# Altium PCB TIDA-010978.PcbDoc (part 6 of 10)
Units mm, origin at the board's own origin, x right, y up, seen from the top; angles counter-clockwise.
Board outline 243.95 x 94.85 mm, 4 copper layers (Top Layer, Mid Layer 1, Mid Layer 2, Bottom Layer), stack 1.623 mm thick; 865 components, 374 nets, 2308 pads, 2132 vias.
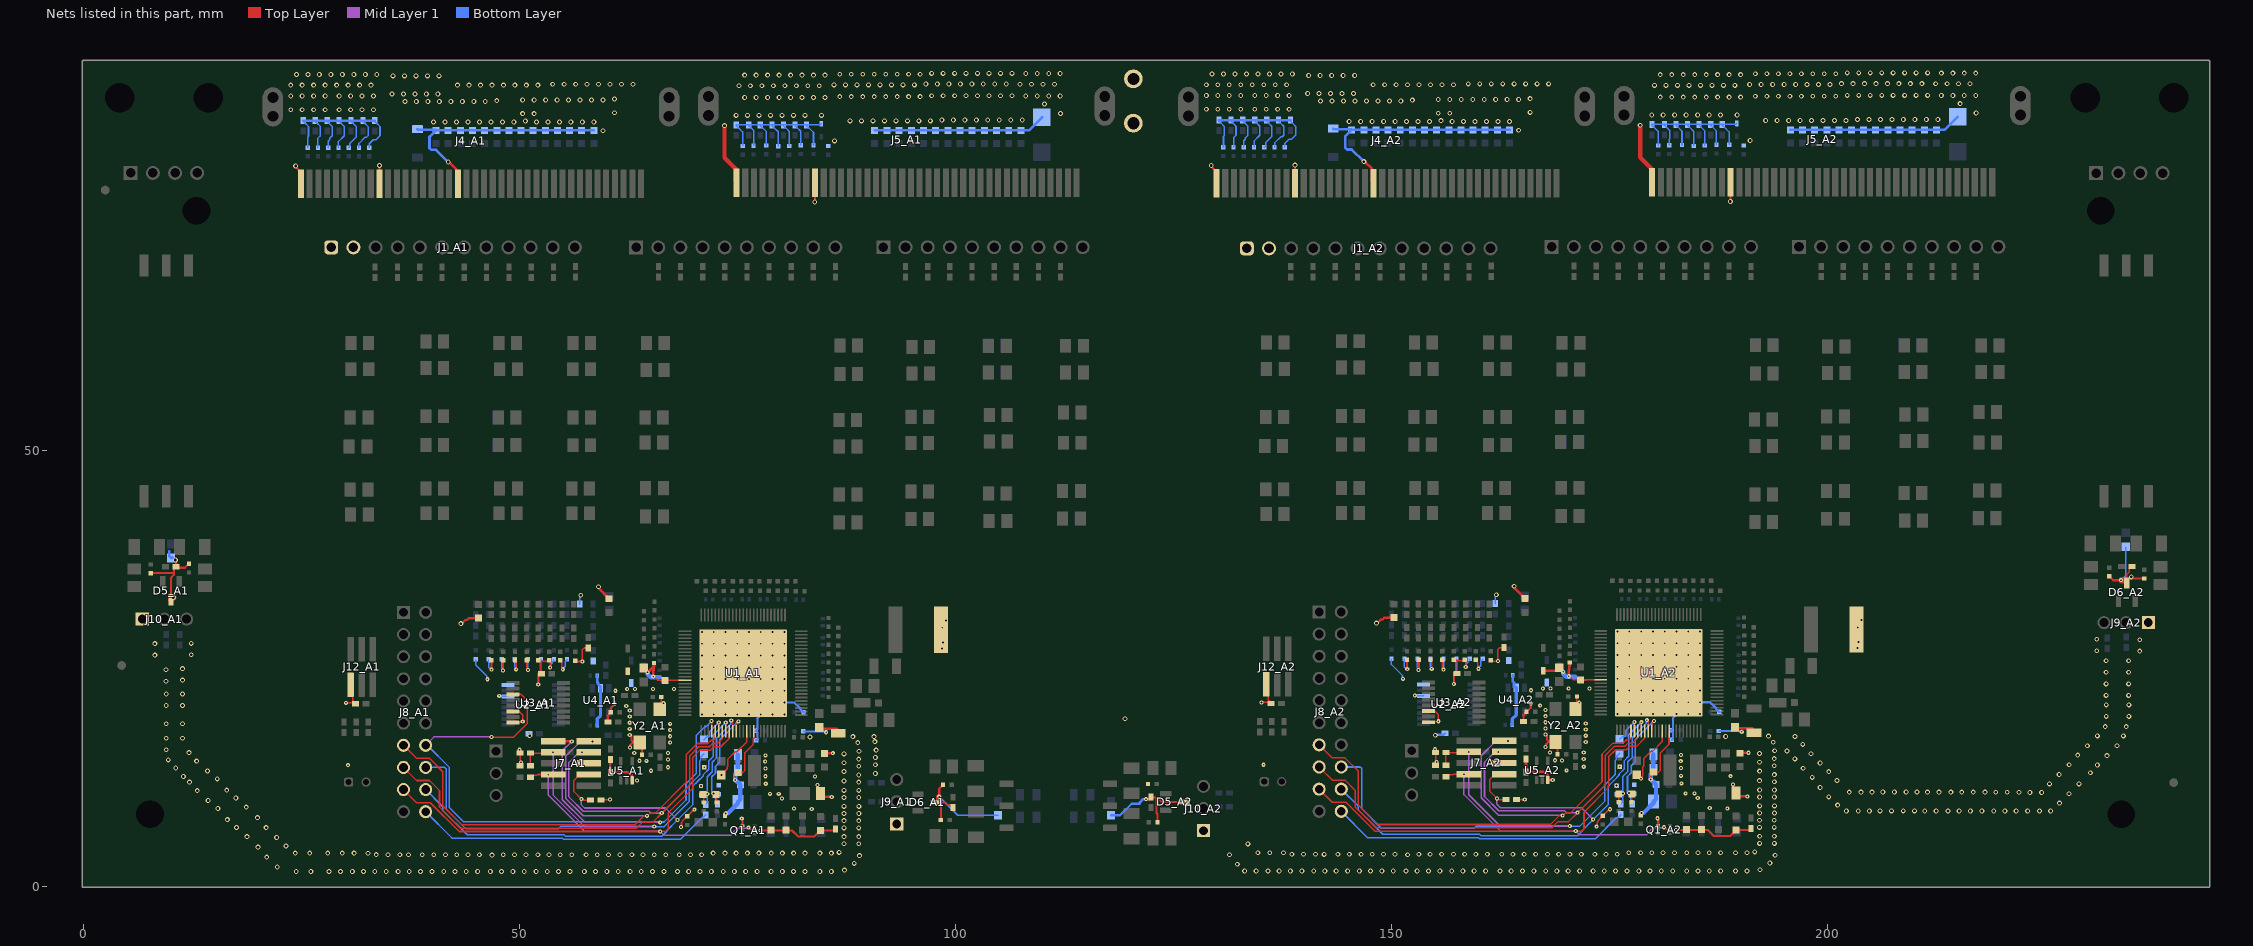
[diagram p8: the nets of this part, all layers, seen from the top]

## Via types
v1: diameter 0.559, hole 0.305, Top Layer to Bottom Layer, tented both sides, 1735 vias
v2: diameter 0.47, hole 0.2, Top Layer to Bottom Layer, tented both sides, 269 vias
v3: diameter 0.5, hole 0.2, Top Layer to Bottom Layer, tented both sides, 128 vias

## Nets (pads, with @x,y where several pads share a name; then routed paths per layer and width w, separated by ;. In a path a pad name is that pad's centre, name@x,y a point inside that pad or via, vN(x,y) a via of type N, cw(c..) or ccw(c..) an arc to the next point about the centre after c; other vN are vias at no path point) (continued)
GND_A1: AVDD_LED1_A1.1 C3.1 C4.1 C9_A1.1 C10_A1.2 C11_A1.1 C16_A1.1 C17_A1.1 C18_A1.2 C19_A1.1 C20_A1.1 C21_A1.1 C22_A1.1 C23_A1.1 C24_A1.1 C29_A1.1 C30_A1.1 C32_A1.2 C33_A1.2 C40_A1.1 C51_A1.2 C52_A1.1 C58_A1.1 C59_A1.2 C60_A1.2 C61_A1.2 C62_A1.2 C63_A1.2 C64_A1.2 C65_A1.2 C66_A1.2 C67_A1.2 C68_A1.2 C69_A1.2 C70_A1.1 C71_A1.1 C72_A1.2 C73_A1.2 C74_A1.1 C75_A1.1 C76_A1.2 C77_A1.2 C78_A1.1 C79_A1.1 C80_A1.2 C81_A1.2 C82_A1.1 C83_A1.1 C84_A1.1 C85_A1.1 C86_A1.1 C87_A1.1 C88_A1.2 C89_A1.1 C90_A1.1 C92_A1.1 C93_A1.1 C94_A1.2 C95_A1.1 C96_A1.1 C98_A1.1 C99_A1.1 C102_A1.1 C103_A1.1 C104_A1.1 C105_A1.1 C108_A1.1 C109_A1.1 C112_A1.1 C113_A1.1 C114_A1.1 C115_A1.1 C118_A1.1 C119_A1.1 C123_A1.1 C124_A1.2 C125_A1.1 C128_A1.2 C129_A1.1 C132_A1.1 C133_A1.1 C134_A1.1 C135_A1.1 C138_A1.2 C139_A1.2 C140_A1.1 C141_A1.1 C142_A1.2 C143_A1.1 C146_A1.1 C147_A1.2 C148_A1.2 C149_A1.1 C150_A1.1 C151_A1.1 C154_A1.1 C155_A1.1 C158_A1.1 C159_A1.2 C160_A1.2 C161_A1.1 C164_A1.1 D1_A1.2 D3_A1.2 D4_A1.2 D5_A1.3 D6_A1.3 D7_A1.2 D8_A1.2 J1_A1.1 J1_A1.2 J4_A1.5 J4_A1.21 J4_A1.30 J5_A1.5 J5_A1.21 J7_A1.5 J9_A1.1 J10_A1.1 J12_A1.6 j13.1 LDOIN_LED1_A1.1 NFAULT_LED1_A1.1 Q1_A1.1 R76_A1.1 R79_A1.1 R141_A1.2 R144_A1.2 R147_A1.2 R150_A1.2 R153_A1.1 R157_A1.2 R160_A1.2 R162_A1.2 R164_A1.2 R165_A1.1 R177_A1.2 R179_A1.2 R181_A1.2 R183_A1.2 R185_A1.1 R187_A1.2 R189_A1.2 R191_A1.2 R236_A1.1 RT1_A1.2 TSREF_LED1_A1.1 U1_A1.65 U1_A1.89 U1_A1.91 U1_A1.101 U2_A1.6 U2_A1.8 U3_A1.6 U3_A1.8 U4_A1.2 U5_A1.3 Y2_A1.2 Y2_A1.4 | length 266.7
  Top Layer w0.178: v2(30.107,21.044) 31.072,21.044 R236_A1.1@31.136,20.98 ; J12_A1.6@30.631,23.126 30.875,22.882 R236_A1.1@30.875,21.141 ; 30.87,21.255 30.97,21.255 R236_A1.1@31.181,21.044 ; U3_A1.8@49.243,18.774 49.299,18.829 50.316,18.829 v2(50.372,18.885) 50.372,19.668 50.088,19.952 49.365,19.952 U3_A1.6@49.243,20.074 ; C80_A1.2@49.482,25.822 49.624,25.681 v2(49.624,24.893) ; R162_A1.2@50.05,13.845 50.071,13.866 C32_A1.2@50.071,15.296 ; C76_A1.2@50.832,25.822 50.832,25.017 50.967,24.882 v2(50.967,24.803) ; v2(52.153,23.151) 52.191,23.19 52.191,24.162 52.394,24.365 C88_A1.2@52.435,24.365 ; C88_A1.2@52.503,24.373 52.444,24.373 C88_A1.2@52.435,24.365 ; v2(53.52,25.113) 53.52,25.705 53.403,25.822 52.162,25.822 52.373,25.611 52.373,24.428 C88_A1.2@52.435,24.365 ; C68_A1.2@54.664,25.822 54.875,25.611 54.875,25.077 54.971,24.982 v2(54.971,24.903) ; C73_A1.2@56.387,25.793 56.387,25.787 v2(57.207,25.787) 57.207,27.132 57.409,27.334 R185_A1.1@57.902,27.334 ; R165_A1.1@59.346,9.902 59.4,9.956 v2(60.397,9.956) ; TSREF_LED1_A1.1@60.292,32.984 TSREF_LED1_A1.1@60.604,32.673 ; v2@65.416,24.049 65.816,23.648 66.685,23.648 C30_A1.1@66.704,23.629 ; Y2_A1.2@66.094,20.313 66.272,20.491 C128_A1.2@66.272,21.722 ; C30_A1.1@66.704,23.615 67.334,23.615 67.367,23.649 U1_A1.65@68.982,23.649 ; v2(68.528,6.8) 68.584,6.856 68.584,7.291 68.651,7.358 68.651,7.462 69.988,8.799 v2(70.055,8.799) ; C21_A1.1@73.142,12.79 73.835,13.483 73.835,13.675 73.906,13.745 73.906,14.597 74.737,15.428 74.924,15.428 76.057,16.561 U1_A1.89@76.057,17.774 ; C40_A1.1@73.615,8.307 v2(73.671,8.363) ; v2(74.737,12.212) 74.761,12.236 74.761,12.774 C22_A1.1@75.044,13.057 75.628,13.057 75.819,13.247 75.819,15.254 76.824,16.259 76.824,16.925 76.856,16.957 76.856,17.772 U1_A1.91@76.857,17.774 ; D6_A1.3@98.325,9.621 98.786,9.621 99.075,9.333 99.497,9.333 99.708,9.121 C143_A1.1@99.708,9.021
  Top Layer w0.254: C149_A1.1@7.717,35.916 7.745,35.944 10.371,35.944 ; D5_A1.3@10.044,33.134 10.044,35.399 10.371,35.726 10.371,35.944 ; 10.371,36.172 10.371,35.944 ; 10.372,36.172 10.372,36.493 10.545,36.666 C142_A1.2@10.633,36.666 ; v1(10.541,37.436) 10.541,37.353 10.645,37.25 10.645,36.666 10.779,36.531 11.628,36.531 C148_A1.2@12.096,37 ; v1(24.331,82.609) 24.39,82.551 24.39,82.44 24.942,81.887 J4_A1.21@24.942,80.587 ; J4_A1.5@33.942,80.587 v1(33.942,82.659) ; v1(43.284,30.133) 43.366,30.133 43.789,30.556 43.974,30.556 44.171,30.753 C24_A1.1@45.296,30.753 ; C77_A1.2@46.781,25.822 46.794,25.809 46.794,24.869 v2(46.807,24.856) ; v2(48.11,24.756) 48.119,24.764 48.119,25.814 C81_A1.2@48.127,25.822 ; R76_A1.1@60.128,18.845 60.128,19.604 C155_A1.1@60.483,19.959 60.483,20.456 v2@60.966,20.939 ; v2(62.672,15.937) 62.713,15.979 62.713,16.216 63.041,16.545 ; v2@62.814,17.364 62.837,17.341 62.837,16.748 63.041,16.545 ; C124_A1.2@64.047,15.088 64.047,16.261 Y2_A1.4@63.794,16.513 63.763,16.545 63.041,16.545 ; C21_A1.1@73.142,12.79 C21_A1.1@73.142,12.765 73.154,12.765 v2(73.156,12.763) ; v2(75.494,7.764) 75.494,7.705 75.587,7.612 Q1_A1.1@75.587,6.965 ; v2(77.639,6.415) 80.524,6.415 LDOIN_LED1_A1.1@80.571,6.462 80.621,6.412 81.267,6.412 81.944,5.735 83.84,5.735 NFAULT_LED1_A1.1@84.517,6.412 86.078,6.412 R79_A1.1@86.233,6.567 ; v1(83.863,78.487) 83.878,78.501 83.878,80.673 J5_A1.5@83.892,80.687 ; C9_A1.1@84.393,18.214 84.521,18.086 85.193,18.086 ; D3_A1.2@84.519,10.671 84.903,10.287 85.768,10.287 v2(85.81,10.246) ; C20_A1.1@84.958,15.215 85.021,15.277 v2(85.933,15.277) ; v2(85.171,17.674) 85.193,17.697 85.193,18.086 ; C19_A1.1@86.559,17.937 86.411,18.086 85.193,18.086 ; D6_A1.3@97.804,9.621 97.956,9.621 D6_A1.3@98.129,9.794 ; C154_A1.1@98.325,7.612 98.325,9.621 98.325,10.029 98.129,10.226 v2(98.129,10.284) 98.129,11.19 C147_A1.2@98.575,11.636
  Top Layer w0.305: v1(41.831,83.062) 41.88,83.013 41.986,83.013 42.745,82.254 42.745,80.785 J4_A1.30@42.942,80.587 ; v1(59.069,34.361) 59.118,34.313 59.118,34.159 TSREF_LED1_A1.1@60.292,32.984 ; C161_A1.1@60.428,14.557 C160_A1.2@60.428,13.078 62.51,13.078 62.889,12.699 62.889,12.205 U5_A1.3@62.937,12.157 ; v2(64.689,24.548) 64.711,24.548 65.339,25.177 ; v2(65.344,24.049) 65.344,24.741 65.38,24.777 65.38,25.191 65.435,25.246 65.435,25.62 C164_A1.1@65.437,25.623
  Top Layer w0.508: v1(73.517,87.237) 73.517,83.547 74.796,82.267 74.796,80.783 J5_A1.21@74.892,80.687
  Top Layer w0.711: D5_A1.3@10.044,32.867 v1(10.311,33.134) ; D6_A1.3@98.129,9.794 v2@98.129,10.226
  Bottom Layer w0.178: R181_A1.2@25.217,87.812 25.217,87.712 25.428,87.501 25.437,87.501 25.806,87.132 25.806,86.036 25.738,85.968 25.738,84.735 C102_A1.1@25.715,84.712 ; R177_A1.2@26.584,87.812 26.584,87.712 26.795,87.501 26.804,87.501 27.173,87.132 27.173,86.092 26.89,85.81 C95_A1.1@26.89,84.712 ; R179_A1.2@27.951,87.812 27.951,87.712 28.162,87.501 28.17,87.501 28.54,87.132 28.54,86.092 28.227,85.78 28.227,85.615 28.066,85.453 C98_A1.1@28.066,84.712 ; C104_A1.1@29.241,84.712 29.241,85.427 29.906,86.092 29.906,87.132 29.537,87.501 29.528,87.501 29.317,87.712 R183_A1.2@29.317,87.812 ; C108_A1.1@30.416,84.712 30.559,84.854 30.559,85.229 31.273,85.943 31.273,87.132 30.904,87.501 30.895,87.501 30.684,87.712 R187_A1.2@30.684,87.812 ; C112_A1.1@31.592,84.712 31.592,85.193 32.322,85.923 32.47,85.923 32.64,86.092 32.64,87.132 32.27,87.501 32.262,87.501 32.051,87.712 R189_A1.2@32.051,87.812 ; C114_A1.1@32.767,84.712 32.767,85.151 33.238,85.622 33.536,85.622 34.006,86.092 34.006,87.132 33.637,87.501 33.628,87.501 33.417,87.712 R191_A1.2@33.417,87.812 ; C64_A1.2@44.997,25.965 44.997,25.391 46.263,24.125 46.263,23.808 v2(46.319,23.753) ; C66_A1.2@46.491,25.965 46.491,25.054 46.53,25.054 46.728,24.856 v2(46.807,24.856) ; v2@47.728,21.904 47.812,21.82 48.642,21.82 U2_A1.6@48.673,21.789 ; C65_A1.2@47.984,25.965 47.984,24.961 48.11,24.835 v2(48.11,24.756) ; C63_A1.2@49.477,25.965 49.477,25.118 49.624,24.972 v2(49.624,24.893) ; v2(50.967,24.803) 50.967,25.961 C61_A1.2@50.971,25.965 ; v2(52.153,23.151) 52.153,24.411 52.464,24.723 52.464,25.904 C60_A1.2@52.464,25.965 ; v2(53.52,25.113) 53.576,25.169 53.576,25.483 53.958,25.865 C59_A1.2@53.958,25.965 ; v2(54.971,24.903) 54.971,24.982 55.24,25.251 55.24,25.754 C62_A1.2@55.451,25.965 ; R153_A1.1@56.902,32.371 56.902,33.157 57.03,33.285 v1(57.03,33.388) ; C158_A1.1@58.902,24.162 C158_A1.1@58.969,24.229 ; v2(65.344,24.049) v2@65.395,24.1 ; C82_A1.1@75.592,84.912 75.592,86.521 75.087,87.026 75.078,87.026 74.867,87.237 R147_A1.2@74.867,87.337 R141_A1.2@76.298,87.337 ; C74_A1.1@76.842,84.937 76.842,85.573 76.887,85.617 76.887,86.657 76.518,87.026 76.509,87.026 76.298,87.237 R141_A1.2@76.298,87.337 ; C78_A1.1@78.317,84.962 78.317,86.553 77.844,87.026 77.835,87.026 77.624,87.237 R144_A1.2@77.624,87.337 ; C84_A1.1@79.667,84.862 79.667,86.529 79.17,87.026 79.162,87.026 78.951,87.237 R150_A1.2@78.951,87.337 ; C86_A1.1@80.942,84.912 80.942,86.58 80.497,87.026 80.488,87.026 80.277,87.237 R157_A1.2@80.277,87.337 ; C89_A1.1@82.267,84.987 82.267,86.582 81.823,87.026 81.815,87.026 81.603,87.237 R160_A1.2@81.603,87.337 ; C92_A1.1@83.717,84.987 83.717,86.458 83.149,87.026 83.141,87.026 82.93,87.237 R164_A1.2@82.93,87.337 ; RT1_A1.2@84.617,87.452 84.617,87.448 84.506,87.337 R164_A1.2@82.93,87.337 ; v2(98.129,10.284) 100.266,8.146 C4.1@104.875,8.146 ; R141_A1.2@76.298,87.337 R144_A1.2@77.624,87.337 ; R144_A1.2@77.624,87.337 R150_A1.2@78.951,87.337 ; R150_A1.2@78.951,87.337 R157_A1.2@80.277,87.337 ; R157_A1.2@80.277,87.337 R160_A1.2@81.603,87.337 ; R160_A1.2@81.603,87.337 R164_A1.2@82.93,87.337
  Bottom Layer w0.254: C67_A1.2@51.118,17.497 51.168,17.447 v1(51.168,17.28) ; C150_A1.1@77.031,17.85 C150_A1.1@77.11,17.85 ; C150_A1.1@77.131,17.85 77.131,17.829 C150_A1.1@77.283,17.677 ; C138_A1.2@77.157,16.76 77.173,16.744 77.283,16.854 C150_A1.1@77.283,17.677 ; v3(77.682,19.724) 77.682,19.657 77.271,19.246 77.283,19.234 77.283,18.023 C150_A1.1@77.11,17.85 ; v3(80.382,21.074) 81.527,21.074 82.206,20.395 82.206,20.332 C139_A1.2@82.579,19.959 C139_A1.2@82.679,19.959 ; C151_A1.1@82.644,17.772 85.014,17.772 85.112,17.674 v2(85.171,17.674) ; 86.233,6.567 86.233,6.667 ; C150_A1.1@77.11,17.85 C150_A1.1@77.283,17.677
  Bottom Layer w0.305: 9.821,38.411 9.821,37.874 C3.1@10.033,37.663 ; C3.1@10.195,37.714 10.473,37.436 v1(10.541,37.436) ; R181_A1.2@25.217,87.812 R177_A1.2@26.584,87.812 R179_A1.2@27.951,87.812 R183_A1.2@29.317,87.812 R187_A1.2@30.684,87.812 R189_A1.2@32.051,87.812 R191_A1.2@33.417,87.812 ; D7_A1.2@38.313,86.844 38.38,86.776 40.372,86.776 C146_A1.1@40.439,86.709 ; v1(41.831,83.062) 40.437,84.456 39.893,84.456 39.687,84.663 39.687,85.956 C146_A1.1@40.439,86.709 ; C109_A1.1@58.533,86.709 C113_A1.1@57.142,86.709 C115_A1.1@55.75,86.709 C119_A1.1@54.358,86.709 C123_A1.1@52.966,86.709 C125_A1.1@51.574,86.709 C129_A1.1@50.182,86.709 C132_A1.1@48.79,86.709 C133_A1.1@47.398,86.709 C134_A1.1@46.007,86.709 C135_A1.1@44.615,86.709 C140_A1.1@43.223,86.709 C141_A1.1@41.831,86.709 C146_A1.1@40.439,86.709 ; C158_A1.1@58.902,24.175 58.902,23.455 59.002,23.354 59.002,23.215 59.3,22.917 U4_A1.2@59.3,22.717 ; C105_A1.1@90.742,86.709 C103_A1.1@92.139,86.709 C99_A1.1@93.536,86.709 C96_A1.1@94.934,86.709 C93_A1.1@96.331,86.709 C90_A1.1@97.728,86.709 C87_A1.1@99.125,86.709 C85_A1.1@100.522,86.709 C83_A1.1@101.919,86.709 C79_A1.1@103.316,86.709 C75_A1.1@104.713,86.709 C71_A1.1@106.11,86.709 108.439,86.709 D1_A1.2@109.917,88.187
  Bottom Layer w0.381: C159_A1.2@58.907,18.454 58.917,18.463 58.917,19.212 59.3,19.595 U4_A1.2@59.3,22.717
  Bottom Layer w0.508: v2(64.689,24.548) 64.689,24.333 65.042,23.979 C58_A1.1@66.054,23.979 ; v2(73.671,8.363) 73.901,8.363 75.064,9.526 C18_A1.2@75.064,9.691 75.337,9.964 75.337,11.506 75.339,11.508 C11_A1.1@75.339,11.652 75.058,11.933 75.016,11.933 v2(74.737,12.212) 74.737,12.838 75.044,13.145 C16_A1.1@75.044,13.345 C17_A1.1@75.044,15.117
  other v1: 24.409,1.712 26.075,1.712 28.165,1.712 29.48,1.712 30.835,1.712 32.114,1.712 33.405,1.712 34.72,1.712 36.084,1.712 37.363,1.712 38.654,1.712 39.969,1.712 41.324,1.712 42.603,1.712 43.894,1.712 45.209,1.712 46.669,1.712 47.947,1.712 49.238,1.712 50.553,1.712 51.909,1.712 53.187,1.712 54.478,1.712 55.793,1.712 57.448,1.712 58.726,1.712 60.018,1.712 61.332,1.712 62.688,1.712 63.966,1.712 65.258,1.712 66.572,1.712 68.127,1.712 69.406,1.712 70.697,1.712 72.012,1.712 73.367,1.712 74.646,1.712 75.937,1.712 77.252,1.712 78.865,1.712 80.144,1.712 81.435,1.712 82.75,1.712 84.454,1.712 85.768,1.712 87.268,1.858 22.225,2.225 88.389,2.633 21.025,3.35 88.991,3.524 46.85,3.578 37.277,3.625 33.573,3.641 34.92,3.632 36.284,3.632 38.854,3.632 40.169,3.632 41.524,3.632 42.803,3.632 44.094,3.632 45.409,3.632 48.147,3.632 49.438,3.632 50.753,3.632 52.109,3.632 53.387,3.632 54.678,3.632 55.993,3.632 57.648,3.632 58.926,3.632 60.218,3.632 61.532,3.632 62.888,3.632 64.166,3.632 65.458,3.632 66.772,3.632 68.327,3.632 69.606,3.632 70.897,3.632 32.627,3.8 24.284,3.812 25.95,3.812 28.015,3.812 29.68,3.812 31.035,3.812 72.212,3.812 73.567,3.812 74.846,3.812 76.137,3.812 77.452,3.812 78.868,3.808 80.147,3.808 81.438,3.808 82.753,3.808 84.454,3.808 85.768,3.808 86.653,3.902 20.025,4.5 23.226,4.638 87.217,4.886 88.91,4.886 22.151,5.613 18.746,5.705 87.217,5.704 88.91,5.704 87.209,6.716 88.902,6.716 17.55,6.75 20.951,6.738 87.209,7.535 88.902,7.535 16.5,7.65 19.951,7.888 87.225,8.36 88.918,8.36 15.413,8.935 18.673,9.093 87.225,9.179 88.918,9.179 14.298,9.847 17.476,10.138 87.217,10.191 88.91,10.191 13.047,10.979 87.217,11.009 88.91,11.009 16.426,11.038 12.17,11.954 88.91,11.948 87.209,12.077 15.34,12.323 11.457,12.604 88.91,12.767 90.817,12.942 87.225,13.17 14.225,13.235 10.579,13.579 88.902,13.779 90.809,13.954 87.209,14.182 12.974,14.367 9.731,14.506 88.902,14.597 90.809,14.772 87.209,15.19 12.096,15.342 88.941,15.502 90.906,15.626 9.495,15.669 88.788,16.478 90.753,16.603 9.495,16.987 11.361,16.987 83.325,17.13 88.232,17.175 90.658,17.175 9.495,18.652 11.361,18.652 9.495,20.743 11.361,20.743 9.495,22.058 11.361,22.058 9.474,23.526 11.354,23.654 9.474,24.841 11.354,24.968 8.195,26.522 12.357,26.559 8.195,27.836 12.357,27.873 86.132,85.487 59.583,86.657 40.15,87.662 41.466,87.662 42.782,87.662 44.099,87.662 45.415,87.662 46.732,87.662 48.048,87.662 49.365,87.662 51.951,87.662 53.268,87.662 54.584,87.662 55.9,87.662 57.217,87.662 58.533,87.662 50.682,87.762 87.91,87.787 89.226,87.787 90.543,87.787 91.859,87.787 93.175,87.787 94.492,87.787 95.808,87.787 97.125,87.787 98.442,87.887 99.759,87.887 101.075,87.887 102.392,87.887 103.708,87.887 105.025,87.887 106.341,87.887 107.658,87.887 74.842,88.412 76.158,88.412 77.475,88.412 78.791,88.412 80.108,88.412 81.424,88.412 82.741,88.412 84.642,88.412 50.367,88.612 51.684,88.612 112.042,88.637 60.9,88.712 23.767,89.062 25.084,89.062 26.4,89.062 27.717,89.062 29.317,89.062 30.634,89.062 31.95,89.062 33.267,89.062 110.217,89.712 36.867,90.012 38.184,90.012 39.5,90.012 40.817,90.012 42.133,90.012 43.45,90.012 44.766,90.012 46.083,90.012 47.4,90.112 50.367,90.187 51.684,90.187 53,90.187 54.317,90.187 55.633,90.187 56.95,90.187 58.266,90.187 59.583,90.187 60.9,90.287 75.827,90.462 77.144,90.462 78.46,90.462 79.776,90.462 81.093,90.462 82.409,90.462 83.726,90.462 85.042,90.462 86.735,90.562 88.051,90.562 89.368,90.562 90.684,90.562 92,90.562 93.317,90.562 94.633,90.562 95.95,90.562 23.767,90.637 25.084,90.637 26.4,90.637 27.717,90.637 29.317,90.637 30.634,90.637 31.95,90.637 33.267,90.637 108.058,90.637 109.375,90.637 110.691,90.637 112.008,90.637 97.267,90.662 98.584,90.662 99.9,90.662 101.217,90.662 102.533,90.662 103.85,90.662 105.166,90.662 106.483,90.662 35.381,90.87 36.697,90.87 38.014,90.87 39.33,90.87 40.647,90.87 75.169,91.812 76.485,91.812 77.802,91.812 79.118,91.812 80.435,91.812 81.751,91.812 83.068,91.812 84.384,91.812 23.767,91.879 25.084,91.879 26.4,91.879 27.717,91.879 29.033,91.879 30.35,91.879 31.666,91.879 32.983,91.879 42.897,91.879 44.214,91.879 45.53,91.879 46.847,91.879 48.163,91.879 49.48,91.879 50.796,91.879 52.113,91.879 86.076,91.912 87.393,91.912 88.709,91.912 90.026,91.912 91.342,91.912 92.659,91.912 93.975,91.912 95.292,91.912 53.805,91.979 55.121,91.979 56.438,91.979 57.754,91.979 59.071,91.979 60.387,91.979 61.704,91.979 63.02,91.979 107.4,91.987 108.716,91.987 110.033,91.987 111.349,91.987 96.609,92.012 97.926,92.012 99.242,92.012 100.558,92.012 101.875,92.012 103.191,92.012 104.508,92.012 105.824,92.012 35.506,92.945 36.822,92.945 38.139,92.945 39.455,92.945 40.772,92.945 75.827,93.037 77.144,93.037 78.46,93.037 79.776,93.037 81.093,93.037 82.409,93.037 83.726,93.037 85.042,93.037 24.426,93.104 25.742,93.104 27.058,93.104 28.375,93.104 29.691,93.104 31.008,93.104 32.324,93.104 33.641,93.104 86.735,93.137 88.051,93.137 89.368,93.137 90.684,93.137 92,93.137 93.317,93.137 94.633,93.137 95.95,93.137 108.058,93.212 109.375,93.212 110.691,93.212 112.008,93.212 97.267,93.237 98.584,93.237 99.9,93.237 101.217,93.237 102.533,93.237 103.85,93.237 105.166,93.237 106.483,93.237
  other v2: 83.519,8.879 81.494,8.934 80.118,10.09 78.74,10.616 79.739,10.616 70.819,11.509 84.173,11.636 78.243,11.769 63.492,12.14 83.897,12.588 78.214,12.63 65.091,13.257 78.214,13.518 71.19,13.66 67.048,13.665 30.34,13.897 57.038,14.136 50.185,14.22 78.178,14.314 64.547,14.395 63.763,14.41 67.048,14.557 78.214,15.024 63.168,15.297 67.048,15.297 50.005,15.671 67.284,16.513 67.284,17.221 62.653,17.364 67.284,17.928 62.653,18.066 67.284,18.636 62.653,18.767 62.653,19.468 62.653,20.169 62.245,20.676 60.978,20.951 66.526,21.006 47.677,21.851 60.992,22.439 62.353,22.626 63.253,22.626 65.317,22.639 67.711,22.636 98.446,27.281 98.558,27.966 98.486,29.645 98.913,30.499
  other v3: 70.932,19.724 72.282,19.724 73.632,19.724 74.982,19.724 76.332,19.724 79.032,19.724 80.382,19.724 70.932,21.074 72.282,21.074 73.632,21.074 74.982,21.074 76.332,21.074 77.682,21.074 79.032,21.074 70.932,22.424 72.282,22.424 73.632,22.424 74.982,22.424 76.332,22.424 77.682,22.424 79.032,22.424 80.382,22.424 70.932,23.774 72.282,23.774 73.632,23.774 74.982,23.774 76.332,23.774 77.682,23.774 79.032,23.774 80.382,23.774 70.932,25.124 72.282,25.124 73.632,25.124 74.982,25.124 76.332,25.124 77.682,25.124 79.032,25.124 80.382,25.124 70.932,26.474 72.282,26.474 73.632,26.474 74.982,26.474 76.332,26.474 77.682,26.474 79.032,26.474 80.382,26.474 70.932,27.824 72.282,27.824 73.632,27.824 74.982,27.824 76.332,27.824 77.682,27.824 79.032,27.824 80.382,27.824 70.932,29.174 72.282,29.174 73.632,29.174 74.982,29.174 76.332,29.174 77.682,29.174 79.032,29.174 80.382,29.174
GND_A2: AVDD_LED1_A2.1 C5.1 C8.1 C9_A2.1 C10_A2.2 C11_A2.1 C16_A2.1 C17_A2.1 C18_A2.2 C19_A2.1 C20_A2.1 C21_A2.1 C22_A2.1 C23_A2.1 C24_A2.1 C29_A2.1 C30_A2.1 C32_A2.2 C33_A2.2 C40_A2.1 C51_A2.2 C52_A2.1 C58_A2.1 C59_A2.2 C60_A2.2 C61_A2.2 C62_A2.2 C63_A2.2 C64_A2.2 C65_A2.2 C66_A2.2 C67_A2.2 C68_A2.2 C69_A2.2 C70_A2.1 C71_A2.1 C72_A2.2 C73_A2.2 C74_A2.1 C75_A2.1 C76_A2.2 C77_A2.2 C78_A2.1 C79_A2.1 C80_A2.2 C81_A2.2 C82_A2.1 C83_A2.1 C84_A2.1 C85_A2.1 C86_A2.1 C87_A2.1 C88_A2.2 C89_A2.1 C90_A2.1 C92_A2.1 C93_A2.1 C94_A2.2 C95_A2.1 C96_A2.1 C98_A2.1 C99_A2.1 C102_A2.1 C103_A2.1 C104_A2.1 C105_A2.1 C108_A2.1 C109_A2.1 C112_A2.1 C113_A2.1 C114_A2.1 C115_A2.1 C118_A2.1 C119_A2.1 C123_A2.1 C124_A2.2 C125_A2.1 C128_A2.2 C129_A2.1 C132_A2.1 C133_A2.1 C134_A2.1 C135_A2.1 C138_A2.2 C139_A2.2 C140_A2.1 C141_A2.1 C142_A2.2 C143_A2.1 C146_A2.1 C147_A2.2 C148_A2.2 C149_A2.1 C150_A2.1 C151_A2.1 C154_A2.1 C155_A2.1 C158_A2.1 C159_A2.2 C160_A2.2 C161_A2.1 C164_A2.1 D1_A2.2 D3_A2.2 D4_A2.2 D5_A2.3 D6_A2.3 D7_A2.2 D8_A2.2 J1_A2.1 J1_A2.2 J4_A2.5 J4_A2.21 J4_A2.30 J5_A2.5 J5_A2.21 J7_A2.5 J9_A2.1 J10_A2.1 J12_A2.6 LDOIN_LED1_A2.1 NFAULT_LED1_A2.1 Q1_A2.1 R76_A2.1 R79_A2.1 R141_A2.2 R144_A2.2 R147_A2.2 R150_A2.2 R153_A2.1 R157_A2.2 R160_A2.2 R162_A2.2 R164_A2.2 R165_A2.1 R177_A2.2 R179_A2.2 R181_A2.2 R183_A2.2 R185_A2.1 R187_A2.2 R189_A2.2 R191_A2.2 R236_A2.1 RT1_A2.2 TSREF_LED1_A2.1 U1_A2.65 U1_A2.89 U1_A2.91 U1_A2.101 U2_A2.6 U2_A2.8 U3_A2.6 U3_A2.8 U4_A2.2 U5_A2.3 Y2_A2.2 Y2_A2.4 | length 268.1
  Top Layer w0.178: v2(135.107,21.094) 136.072,21.094 R236_A2.1@136.136,21.03 ; J12_A2.6@135.631,23.176 135.875,22.932 135.875,21.305 ; 135.87,21.305 135.875,21.305 ; R236_A2.1@135.875,21.191 135.875,21.305 ; R236_A2.1@136.181,21.094 135.97,21.305 135.875,21.305 ; U3_A2.8@154.243,18.824 154.299,18.879 155.316,18.879 v2(155.372,18.935) 155.372,19.718 155.088,20.002 154.365,20.002 U3_A2.6@154.243,20.124 ; C80_A2.2@154.482,25.872 154.624,25.731 v2(154.624,24.943) ; R162_A2.2@155.05,13.895 155.071,13.916 C32_A2.2@155.071,15.346 ; C76_A2.2@155.832,25.872 155.832,25.067 155.967,24.932 v2(155.967,24.853) ; v2(157.153,23.201) 157.191,23.24 157.191,24.212 157.394,24.415 C88_A2.2@157.435,24.415 ; C88_A2.2@157.503,24.423 157.444,24.423 C88_A2.2@157.435,24.415 ; v2(158.52,25.163) 158.52,25.755 158.403,25.872 157.162,25.872 157.373,25.661 157.373,24.478 C88_A2.2@157.435,24.415 ; C68_A2.2@159.664,25.872 159.875,25.661 159.875,25.127 159.971,25.032 v2(159.971,24.953) ; C73_A2.2@161.387,25.843 161.387,25.837 v2(162.207,25.837) 162.207,27.182 162.409,27.384 R185_A2.1@162.902,27.384 ; R165_A2.1@164.346,9.952 164.353,9.959 v2(165.282,9.959) ; TSREF_LED1_A2.1@165.293,33.034 TSREF_LED1_A2.1@165.604,32.723 ; v2@170.416,24.099 170.816,23.698 171.685,23.698 C30_A2.1@171.704,23.679 ; Y2_A2.2@171.094,20.363 171.272,20.541 C128_A2.2@171.272,21.772 ; C30_A2.1@171.704,23.665 172.334,23.665 172.367,23.699 U1_A2.65@173.982,23.699 ; v2(173.528,6.85) 173.584,6.906 173.584,7.341 173.651,7.408 173.651,7.512 C33_A2.2@174.228,8.089 174.988,8.849 v2(175.055,8.849) ; v2(178.604,12.353) 178.604,12.432 178.835,12.663 178.835,13.725 178.906,13.795 178.906,14.647 179.737,15.478 179.924,15.478 181.057,16.611 U1_A2.89@181.057,17.824 ; C40_A2.1@178.615,8.357 v2(178.671,8.413) ; v2(179.737,12.262) 179.761,12.286 179.761,12.824 C22_A2.1@180.044,13.107 180.628,13.107 180.819,13.297 180.819,15.304 181.824,16.309 181.824,16.975 181.856,17.007 U1_A2.91@181.857,17.824 U1_A2.91@181.857,17.824 ; D6_A2.3@234.331,34.94 234.331,35.309 234.331,35.771 234.62,36.059 234.62,36.481 234.831,36.692 C143_A2.1@234.931,36.692
  Top Layer w0.254: v2(121.842,9.999) 122.246,9.999 122.419,10.172 C142_A2.2@122.419,10.271 ; C142_A2.2@122.523,10.282 122.523,10.251 122.592,10.182 122.969,10.182 123.046,10.105 123.046,9.861 ; C149_A2.1@123.169,7.355 123.169,8.298 123.046,8.421 123.046,9.861 ; D5_A2.3@126.217,9.682 123.685,9.682 123.358,10.009 123.194,10.009 123.046,9.861 ; v1(129.331,82.659) 129.39,82.601 129.39,82.49 129.942,81.937 J4_A2.21@129.942,80.637 ; J4_A2.5@138.942,80.637 v1(138.942,82.709) ; v1(148.284,30.183) 148.366,30.183 148.789,30.606 148.974,30.606 149.171,30.803 C24_A2.1@150.296,30.803 ; C77_A2.2@151.781,25.872 151.794,25.859 151.794,24.919 v2(151.807,24.906) ; v2(153.11,24.806) 153.119,24.814 153.119,25.864 C81_A2.2@153.127,25.872 ; R76_A2.1@165.128,18.895 165.128,19.654 C155_A2.1@165.483,20.009 165.966,20.491 165.966,20.989 v2(165.978,21.001) ; D8_A2.2@167.422,24.724 169.505,24.724 169.63,24.598 v2(169.689,24.598) ; v2(167.672,15.987) 167.713,16.029 167.713,16.266 168.041,16.595 ; v2@167.814,17.414 167.837,17.391 167.837,16.798 168.041,16.595 ; C124_A2.2@169.047,15.138 169.047,16.311 Y2_A2.4@168.794,16.563 168.763,16.595 168.041,16.595 ; C21_A2.1@178.142,12.815 178.142,12.79 178.579,12.353 v2(178.604,12.353) ; v2(180.494,7.814) 180.494,7.755 180.587,7.662 Q1_A2.1@180.587,7.015 ; v2(182.639,6.465) 185.524,6.465 LDOIN_LED1_A2.1@185.571,6.513 185.622,6.462 186.267,6.462 186.944,5.785 188.84,5.785 189.517,6.462 191.078,6.462 R79_A2.1@191.233,6.617 ; v1(188.863,78.537) 188.878,78.551 188.878,80.723 J5_A2.5@188.892,80.737 ; C9_A2.1@189.393,18.264 189.521,18.136 190.193,18.136 ; D3_A2.2@189.519,10.721 189.903,10.337 190.768,10.337 v2(190.81,10.296) ; C20_A2.1@189.958,15.265 190.021,15.327 v2(190.933,15.327) ; v2(190.171,17.724) 190.193,17.747 190.193,18.136 ; C19_A2.1@191.559,17.987 191.411,18.136 190.193,18.136 ; C147_A2.2@232.316,35.559 232.763,35.113 v2(233.668,35.113) ; D6_A2.3@234.158,35.113 234.331,34.94 D6_A2.3@234.331,34.788 ; D6_A2.3@234.331,35.309 v1@234.837,35.309 ; v1(234.837,35.491) v1@234.837,35.309 ; C154_A2.1@236.341,35.309 v1@234.837,35.309
  Top Layer w0.305: v1(146.831,83.112) 146.88,83.063 146.986,83.063 147.745,82.304 147.745,80.835 J4_A2.30@147.942,80.637 ; v1(164.069,34.411) 164.118,34.363 164.118,34.209 TSREF_LED1_A2.1@165.293,33.034 ; C161_A2.1@165.428,14.607 C160_A2.2@165.428,13.128 167.51,13.128 167.889,12.749 167.889,12.255 U5_A2.3@167.937,12.207 167.945,12.198 168.483,12.198 v2(168.492,12.19) ; v2(170.344,24.099) 170.344,24.791 170.38,24.827 170.38,25.241 170.435,25.296 170.435,25.67 C164_A2.1@170.437,25.673
  Top Layer w0.508: v1(178.517,87.287) 178.517,83.597 179.796,82.317 179.796,80.833 J5_A2.21@179.892,80.737
  Top Layer w0.711: v2@233.727,35.113 D6_A2.3@234.158,35.113
  Bottom Layer w0.178: R181_A2.2@130.217,87.862 130.217,87.762 130.428,87.551 130.437,87.551 130.806,87.182 130.806,86.086 130.738,86.018 130.738,84.785 C102_A2.1@130.715,84.762 ; R177_A2.2@131.584,87.862 131.584,87.762 131.795,87.551 131.804,87.551 132.173,87.182 132.173,86.142 131.89,85.86 C95_A2.1@131.89,84.762 ; R179_A2.2@132.951,87.862 132.951,87.762 133.162,87.551 133.17,87.551 133.54,87.182 133.54,86.142 133.227,85.83 133.227,85.665 133.066,85.503 C98_A2.1@133.066,84.762 ; C104_A2.1@134.241,84.762 134.241,85.477 134.906,86.142 134.906,87.182 134.537,87.551 134.528,87.551 134.317,87.762 R183_A2.2@134.317,87.862 ; C108_A2.1@135.416,84.762 135.559,84.904 135.559,85.279 136.273,85.993 136.273,87.182 135.904,87.551 135.895,87.551 135.684,87.762 R187_A2.2@135.684,87.862 ; C112_A2.1@136.592,84.762 136.592,85.243 137.322,85.973 137.47,85.973 137.64,86.142 137.64,87.182 137.27,87.551 137.262,87.551 137.051,87.762 R189_A2.2@137.051,87.862 ; C114_A2.1@137.767,84.762 137.767,85.201 138.238,85.672 138.536,85.672 139.006,86.142 139.006,87.182 138.637,87.551 138.628,87.551 138.417,87.762 R191_A2.2@138.417,87.862 ; C64_A2.2@149.997,26.015 149.997,25.441 151.263,24.175 151.263,23.858 v2(151.319,23.803) ; C66_A2.2@151.491,26.015 151.491,25.104 151.53,25.104 151.728,24.906 v2(151.807,24.906) ; v2@152.728,21.954 152.812,21.87 153.642,21.87 U2_A2.6@153.673,21.839 ; C65_A2.2@152.984,26.015 152.984,25.011 153.11,24.885 v2(153.11,24.806) ; C63_A2.2@154.477,26.015 154.477,25.168 154.624,25.022 v2(154.624,24.943) ; v2(155.967,24.853) 155.967,26.011 C61_A2.2@155.971,26.015 ; v2(157.153,23.201) 157.153,24.461 157.464,24.773 C60_A2.2@157.464,25.954 ; C60_A2.2@157.464,25.954 C60_A2.2@157.464,26.015 ; v2(158.52,25.163) 158.576,25.219 158.576,25.533 158.958,25.915 C59_A2.2@158.958,26.015 ; v2(159.971,24.953) 159.971,25.032 160.24,25.301 160.24,25.804 C62_A2.2@160.451,26.015 ; R153_A2.1@161.902,32.421 161.902,33.207 162.03,33.335 v1(162.03,33.438) ; C158_A2.1@163.902,24.212 C158_A2.1@163.969,24.279 ; C82_A2.1@180.592,84.962 180.592,86.571 180.087,87.076 180.078,87.076 179.867,87.287 R147_A2.2@179.867,87.387 R141_A2.2@181.298,87.387 ; C74_A2.1@181.842,84.987 181.842,85.623 181.887,85.667 181.887,86.707 181.518,87.076 181.509,87.076 181.298,87.287 R141_A2.2@181.298,87.387 ; C78_A2.1@183.317,85.012 183.317,86.603 182.844,87.076 182.835,87.076 182.624,87.287 R144_A2.2@182.624,87.387 ; C84_A2.1@184.667,84.912 184.667,86.579 184.17,87.076 184.162,87.076 183.951,87.287 R150_A2.2@183.951,87.387 ; C86_A2.1@185.942,84.962 185.942,86.63 185.497,87.076 185.488,87.076 185.277,87.287 R157_A2.2@185.277,87.387 ; C89_A2.1@187.267,85.037 187.267,86.632 186.823,87.076 186.815,87.076 186.603,87.287 R160_A2.2@186.603,87.387 ; C92_A2.1@188.717,85.037 188.717,86.508 188.149,87.076 188.141,87.076 187.93,87.287 R164_A2.2@187.93,87.387 ; RT1_A2.2@189.617,87.502 189.617,87.498 189.506,87.387 R164_A2.2@187.93,87.387 ; v2(233.668,35.113) 234.192,35.637 C8.1@234.192,38.865 ; R141_A2.2@181.298,87.387 R144_A2.2@182.624,87.387 ; R144_A2.2@182.624,87.387 R150_A2.2@183.951,87.387 ; R150_A2.2@183.951,87.387 R157_A2.2@185.277,87.387 ; R157_A2.2@185.277,87.387 R160_A2.2@186.603,87.387 ; R160_A2.2@186.603,87.387 R164_A2.2@187.93,87.387
  Bottom Layer w0.254: C5.1@117.849,8.146 118.874,8.146 120.214,9.487 ; v1(155.036,17.33) 155.094,17.388 155.96,17.388 C67_A2.2@156.118,17.547 ; C150_A2.1@182.031,17.9 C150_A2.1@182.11,17.9 ; C150_A2.1@182.131,17.9 C150_A2.1@182.131,17.879 ; C138_A2.2@182.157,16.81 182.173,16.794 182.283,16.904 182.283,17.727 C150_A2.1@182.131,17.879 ; v3(182.682,19.774) 182.682,19.707 182.271,19.296 182.283,19.284 182.283,18.073 C150_A2.1@182.11,17.9 ; v3(185.382,21.124) 186.527,21.124 187.206,20.445 187.206,20.382 C139_A2.2@187.579,20.009 C139_A2.2@187.679,20.009 ; C151_A2.1@187.644,17.822 190.014,17.822 190.112,17.724 v2(190.171,17.724) ; 191.233,6.617 191.233,6.717 ; C150_A2.1@182.11,17.9 C150_A2.1@182.131,17.879
  Bottom Layer w0.305: 120.214,9.487 121.142,9.487 121.142,9.635 121.506,9.999 v2(121.842,9.999) ; R181_A2.2@130.217,87.862 R177_A2.2@131.584,87.862 R179_A2.2@132.951,87.862 R183_A2.2@134.317,87.862 R187_A2.2@135.684,87.862 R189_A2.2@137.051,87.862 R191_A2.2@138.417,87.862 ; D7_A2.2@143.313,86.894 143.38,86.826 145.372,86.826 C146_A2.1@145.439,86.759 ; v1(146.831,83.112) 145.437,84.506 144.893,84.506 144.687,84.713 144.687,86.006 C146_A2.1@145.439,86.759 ; C109_A2.1@163.533,86.759 C113_A2.1@162.142,86.759 C115_A2.1@160.75,86.759 C119_A2.1@159.358,86.759 C123_A2.1@157.966,86.759 C125_A2.1@156.574,86.759 C129_A2.1@155.182,86.759 C132_A2.1@153.79,86.759 C133_A2.1@152.398,86.759 C134_A2.1@151.007,86.759 C135_A2.1@149.615,86.759 C140_A2.1@148.223,86.759 C141_A2.1@146.831,86.759 C146_A2.1@145.439,86.759 ; C158_A2.1@163.902,24.225 163.902,23.505 164.052,23.354 164.052,22.824 164.243,22.824 U4_A2.2@164.3,22.767 ; C105_A2.1@195.742,86.759 C103_A2.1@197.139,86.759 C99_A2.1@198.536,86.759 C96_A2.1@199.934,86.759 C93_A2.1@201.331,86.759 C90_A2.1@202.728,86.759 C87_A2.1@204.125,86.759 C85_A2.1@205.522,86.759 C83_A2.1@206.919,86.759 C79_A2.1@208.316,86.759 C75_A2.1@209.713,86.759 C71_A2.1@211.11,86.759 213.439,86.759 D1_A2.2@214.917,88.237
  Bottom Layer w0.381: C159_A2.2@163.855,18.501 163.855,19.2 164.3,19.645 U4_A2.2@164.3,22.767
  Bottom Layer w0.508: v2(169.689,24.598) 169.689,24.383 170.042,24.029 C58_A2.1@171.054,24.029 ; v2(178.671,8.413) 178.901,8.413 180.064,9.576 C18_A2.2@180.064,9.741 180.337,10.014 180.337,11.556 180.339,11.558 C11_A2.1@180.339,11.702 180.058,11.983 180.016,11.983 v2(179.737,12.262) 179.737,12.888 180.044,13.195 C16_A2.1@180.044,13.395 C17_A2.1@180.044,15.167
  other v1: 133.165,1.762 134.48,1.762 135.835,1.762 137.114,1.762 138.405,1.762 139.72,1.762 141.084,1.762 142.363,1.762 143.654,1.762 144.969,1.762 146.324,1.762 147.603,1.762 148.894,1.762 150.209,1.762 151.669,1.762 152.947,1.762 154.238,1.762 155.553,1.762 156.909,1.762 158.187,1.762 159.478,1.762 160.793,1.762 162.448,1.762 163.726,1.762 165.018,1.762 166.332,1.762 167.688,1.762 168.966,1.762 170.258,1.762 171.572,1.762 173.127,1.762 174.406,1.762 175.697,1.762 177.012,1.762 178.367,1.762 179.646,1.762 180.937,1.762 182.252,1.762 183.865,1.762 185.144,1.762 186.435,1.762 187.75,1.762 189.454,1.762 190.768,1.762 192.268,1.908 132.323,2.53 193.389,2.683 193.991,3.574 131.426,3.628 151.85,3.628 142.277,3.675 138.573,3.691 139.92,3.682 141.284,3.682 143.854,3.682 145.169,3.682 146.524,3.682 147.803,3.682 149.094,3.682 150.409,3.682 153.147,3.682 154.438,3.682 155.753,3.682 157.109,3.682 158.387,3.682 159.678,3.682 160.993,3.682 162.648,3.682 163.926,3.682 165.218,3.682 166.532,3.682 167.888,3.682 169.166,3.682 170.458,3.682 171.772,3.682 173.327,3.682 174.606,3.682 175.897,3.682 137.627,3.85 134.68,3.862 136.035,3.862 177.212,3.862 178.567,3.862 179.846,3.862 181.137,3.862 182.452,3.862 183.868,3.858 185.147,3.858 186.438,3.858 187.753,3.858 189.454,3.858 190.768,3.858 191.653,3.952 133.536,4.871 192.217,4.936 193.91,4.936 192.217,5.754 193.91,5.754 192.209,6.766 193.902,6.766 192.209,7.585 193.902,7.585 192.225,8.41 193.918,8.41 202.168,8.65 203.524,8.65 204.802,8.65 211.15,8.65 212.465,8.65 213.82,8.65 215.099,8.65 216.39,8.65 217.705,8.65 219.069,8.65 220.347,8.65 221.639,8.65 222.953,8.65 224.309,8.65 225.587,8.65 206.025,8.66 207.34,8.66 208.695,8.66 209.974,8.66 192.225,9.229 193.918,9.229 201.165,9.318 226.6,9.546 192.217,10.241 193.91,10.241 200.15,10.259 227.7,10.622 223.205,10.768 224.561,10.768 202.493,10.808 203.849,10.808 205.104,10.808 211.475,10.808 212.79,10.808 214.145,10.808 215.4,10.808 216.715,10.808 218.07,10.808 219.3,10.8 220.615,10.8 221.97,10.8 206.35,10.818 207.665,10.818 209.02,10.818 210.275,10.818 192.217,11.059 193.91,11.059 199.156,11.337 225.464,11.75 228.85,11.75 193.91,11.998 192.209,12.127 201.097,12.139 198.254,12.496 193.91,12.817 226.564,12.826 230.15,13.025 200.15,13.16 192.225,13.22 197.206,13.545 193.902,13.829 230.95,13.921 227.714,13.954 199.156,14.157 192.209,14.232 196.256,14.626 193.902,14.647 232.05,14.997 228.7,15.05 198.107,15.206 192.209,15.24 195.366,15.519 193.941,15.552 229.8,16.126 233.2,16.126 197.157,16.287 193.788,16.528 188.325,17.18 196.267,17.18 193.232,17.225 230.95,17.254 233.925,17.254 231.858,18.324 234.256,18.324 119.438,19.216 231.975,19.5 234.566,19.5 231.975,20.815 234.566,20.815 231.95,21.91 234.541,21.91 231.95,23.225 234.541,23.225 231.95,24.56 234.541,24.56 231.95,25.875 234.541,25.875 235.806,26.972 230.875,27.018 235.806,28.286 230.875,28.333 191.132,85.537 164.583,86.707 145.15,87.712 146.466,87.712 147.782,87.712 149.099,87.712 150.415,87.712 151.732,87.712 153.048,87.712 154.365,87.712 156.951,87.712 158.268,87.712 159.584,87.712 160.9,87.712 162.217,87.712 163.533,87.712 155.682,87.812 192.91,87.837 194.226,87.837 195.543,87.837 196.859,87.837 198.175,87.837 199.492,87.837 200.808,87.837 202.125,87.837 203.442,87.937 204.759,87.937 206.075,87.937 207.392,87.937 208.708,87.937 210.025,87.937 211.341,87.937 212.658,87.937 179.842,88.462 181.158,88.462 182.475,88.462 183.791,88.462 185.108,88.462 186.424,88.462 187.741,88.462 189.642,88.462 155.367,88.662 156.684,88.662 217.042,88.687 165.9,88.762 128.767,89.112 130.084,89.112 131.4,89.112 132.717,89.112 134.317,89.112 135.634,89.112 136.95,89.112 138.267,89.112 215.217,89.762 141.867,90.062 143.184,90.062 144.5,90.062 145.817,90.062 147.133,90.062 148.45,90.062 149.766,90.062 151.083,90.062 152.4,90.162 155.367,90.237 156.684,90.237 158,90.237 159.317,90.237 160.633,90.237 161.95,90.237 163.266,90.237 164.583,90.237 165.9,90.337 180.827,90.512 182.144,90.512 183.46,90.512 184.776,90.512 186.093,90.512 187.409,90.512 188.726,90.512 190.042,90.512 191.735,90.612 193.051,90.612 194.368,90.612 195.684,90.612 197,90.612 198.317,90.612 199.633,90.612 200.95,90.612 128.767,90.687 130.084,90.687 131.4,90.687 132.717,90.687 134.317,90.687 135.634,90.687 136.95,90.687 138.267,90.687 213.058,90.687 214.375,90.687 215.691,90.687 217.008,90.687 202.267,90.712 203.584,90.712 204.9,90.712 206.217,90.712 207.533,90.712 208.85,90.712 210.166,90.712 211.483,90.712 140.381,90.92 141.697,90.92 143.014,90.92 144.33,90.92 145.647,90.92 180.169,91.862 181.485,91.862 182.802,91.862 184.118,91.862 185.435,91.862 186.751,91.862 188.068,91.862 189.384,91.862 128.767,91.929 130.084,91.929 131.4,91.929 132.717,91.929 134.033,91.929 135.35,91.929 136.666,91.929 137.983,91.929 147.897,91.929 149.214,91.929 150.53,91.929 151.847,91.929 153.163,91.929 154.48,91.929 155.796,91.929 157.113,91.929 191.076,91.962 192.393,91.962 193.709,91.962 195.026,91.962 196.342,91.962 197.659,91.962 198.975,91.962 200.292,91.962 158.805,92.029 160.121,92.029 161.438,92.029 162.754,92.029 164.071,92.029 165.387,92.029 166.704,92.029 168.02,92.029 212.4,92.037 213.716,92.037 215.033,92.037 216.349,92.037 201.609,92.062 202.926,92.062 204.242,92.062 205.558,92.062 206.875,92.062 208.191,92.062 209.508,92.062 210.824,92.062 140.506,92.995 141.822,92.995 143.139,92.995 144.455,92.995 145.772,92.995 180.827,93.087 182.144,93.087 183.46,93.087 184.776,93.087 186.093,93.087 187.409,93.087 188.726,93.087 190.042,93.087 129.426,93.154 130.742,93.154 132.058,93.154 133.375,93.154 134.691,93.154 136.008,93.154 137.324,93.154 138.641,93.154 191.735,93.187 193.051,93.187 194.368,93.187 195.684,93.187 197,93.187 198.317,93.187 199.633,93.187 200.95,93.187 213.058,93.262 214.375,93.262 215.691,93.262 217.008,93.262 202.267,93.287 203.584,93.287 204.9,93.287 206.217,93.287 207.533,93.287 208.85,93.287 210.166,93.287 211.483,93.287
  other v2: 188.519,8.929 186.494,8.984 185.118,10.14 183.74,10.666 184.739,10.666 175.819,11.559 189.173,11.686 183.243,11.819 188.897,12.638 183.214,12.68 170.091,13.307 183.214,13.568 176.19,13.71 172.048,13.715 135.34,13.947 162.038,14.186 155.185,14.27 183.178,14.364 169.547,14.445 168.763,14.46 172.048,14.607 183.214,15.074 168.168,15.347 172.048,15.347 155.005,15.721 172.284,16.563 172.284,17.271 167.653,17.414 172.284,17.978 167.653,18.116 172.284,18.686 167.653,18.817 167.653,19.518 167.653,20.219 167.053,20.726 171.526,21.056 152.677,21.901 165.992,22.489 167.358,22.701 168.233,22.701 170.317,22.689 172.711,22.686 203.446,27.331 203.558,28.016 203.486,29.695 203.913,30.549
  other v3: 175.932,19.774 177.282,19.774 178.632,19.774 179.982,19.774 181.332,19.774 184.032,19.774 185.382,19.774 175.932,21.124 177.282,21.124 178.632,21.124 179.982,21.124 181.332,21.124 182.682,21.124 184.032,21.124 175.932,22.474 177.282,22.474 178.632,22.474 179.982,22.474 181.332,22.474 182.682,22.474 184.032,22.474 185.382,22.474 175.932,23.824 177.282,23.824 178.632,23.824 179.982,23.824 181.332,23.824 182.682,23.824 184.032,23.824 185.382,23.824 175.932,25.174 177.282,25.174 178.632,25.174 179.982,25.174 181.332,25.174 182.682,25.174 184.032,25.174 185.382,25.174 175.932,26.524 177.282,26.524 178.632,26.524 179.982,26.524 181.332,26.524 182.682,26.524 184.032,26.524 185.382,26.524 175.932,27.874 177.282,27.874 178.632,27.874 179.982,27.874 181.332,27.874 182.682,27.874 184.032,27.874 185.382,27.874 175.932,29.224 177.282,29.224 178.632,29.224 179.982,29.224 181.332,29.224 182.682,29.224 184.032,29.224 185.382,29.224
GPIO1_A1: C38_A1.2 C52_A1.2 R57_A1.1 R105_A1.2 U1_A1.86 | length 13.8
  Top Layer w0.178: C38_A1.2@72.562,10.548 72.629,10.481 R57_A1.1@72.629,9.633 ; U1_A1.86@74.857,17.774 74.868,17.785 74.868,18.555 74.868,18.589 74.928,18.649 74.928,18.661 75.112,18.845 v2(75.112,18.924)
  Bottom Layer w0.178: v2@72.064,10.637 72.064,12.563 72.484,12.982 72.484,13.779 72.976,14.271 72.976,16.828 74.782,18.634 74.782,18.692 74.886,18.796 74.905,18.796 75.033,18.924 v2(75.112,18.924) ; v2@72.247,10.585 72.448,10.383 72.448,10.113 72.486,10.075 72.486,9.637 R105_A1.2@72.697,9.426 ; v2(72.247,10.664) 72.286,10.624 72.814,10.624 C52_A1.2@72.854,10.585
GPIO1_A2: C38_A2.2 C52_A2.2 R57_A2.1 R105_A2.2 U1_A2.86 | length 13.8
  Top Layer w0.178: R57_A2.1@177.531,9.65 177.531,10.567 C38_A2.2@177.562,10.598 ; U1_A2.86@179.857,17.824 179.868,17.835 179.868,18.605 179.868,18.639 179.928,18.699 179.928,18.711 180.112,18.895 v2(180.112,18.974)
  Bottom Layer w0.178: v2@177.064,10.687 177.064,12.613 177.484,13.032 177.484,13.829 177.976,14.321 177.976,16.878 179.782,18.684 179.782,18.742 179.886,18.846 179.905,18.846 180.033,18.974 v2(180.112,18.974) ; v2@177.247,10.635 177.448,10.433 177.448,9.635 R105_A2.2@177.609,9.474 ; v2(177.247,10.714) 177.286,10.674 177.814,10.674 C52_A2.2@177.854,10.635
GPIO2_A1: C38_A1.1 C51_A1.1 R55_A1.1 R78_A1.1 U1_A1.85 | length 14.3
  Top Layer w0.178: C38_A1.1@70.911,10.542 C38_A1.1@70.917,10.548 ; R55_A1.1@71.154,9.635 71.154,10.457 C38_A1.1@71.062,10.548 71.113,10.599 v2(71.54,10.599) ; v2(74.286,19.014) 74.286,18.935 74.456,18.765 74.456,17.775 U1_A1.85@74.457,17.774
  Bottom Layer w0.178: C51_A1.1@70.819,10.509 70.864,10.554 71.496,10.554 v2(71.54,10.599) ; R78_A1.1@71.375,9.412 71.375,9.455 71.54,9.62 v2(71.54,10.599) ; v2(74.286,19.014) 74.231,18.958 74.231,18.617 72.599,16.985 72.599,14.726 72.106,14.233 72.106,13.138 71.54,12.573 v2(71.54,10.599)
GPIO2_A2: C38_A2.1 C51_A2.1 R55_A2.1 R78_A2.1 U1_A2.85 | length 14.4
  Top Layer w0.178: C38_A2.1@175.911,10.592 C38_A2.1@175.917,10.598 ; R55_A2.1@176.056,9.653 176.062,9.653 C38_A2.1@176.062,10.598 176.113,10.649 v2(176.54,10.649) ; v2(179.286,19.064) 179.286,18.985 179.456,18.815 179.456,17.825 U1_A2.85@179.457,17.824
  Bottom Layer w0.178: C51_A2.1@175.819,10.559 175.864,10.604 176.496,10.604 v2(176.54,10.649) ; R78_A2.1@176.287,9.461 176.498,9.672 176.498,10.105 176.54,10.148 v2(176.54,10.649) ; v2(179.286,19.064) 179.231,19.008 179.231,18.667 177.599,17.035 177.599,14.776 177.106,14.283 177.106,13.188 176.54,12.623 v2(176.54,10.649)
GPIO2_R_A1: J8_A1.20 R78_A1.2 | length 34.6
  Bottom Layer w0.178: J8_A1.20@39.243,8.561 42.264,5.54 54.947,5.54 55.092,5.395 68.475,5.395 71.084,8.003 71.166,8.003 R78_A1.2@71.375,8.212
GPIO2_R_A2: J8_A2.20 R78_A2.2 | length 34.6
  Bottom Layer w0.178: J8_A2.20@144.243,8.611 147.264,5.59 159.947,5.59 160.092,5.445 173.355,5.445 175.786,7.876 175.883,7.876 175.957,7.949 176.076,7.949 176.287,8.161 R78_A2.2@176.287,8.261
GPIO3_A1: J7_A1.4 J8_A1.17 Q1_A1.5 R155_A1.1 U1_A1.84 | length 78.4
  Top Layer w0.178: J8_A1.17@36.703,11.101 38.204,9.6 39.784,9.6 43.093,6.291 66.129,6.291 v2(66.135,6.296) 66.819,6.296 67.08,6.558 67.08,8.462 69.896,11.278 69.896,14.808 70.714,15.626 71.917,15.626 72.295,16.004 72.56,16.004 73.092,16.004 74.046,16.958 74.046,17.092 74.046,17.762 U1_A1.84@74.057,17.774 ; R155_A1.1@51.265,12.523 51.365,12.523 51.576,12.734 52.017,12.734 52.113,12.831 53.342,12.831 v2(53.311,12.799) ; v2(76.247,6.732) 76.326,6.732 76.533,6.526 76.876,6.526 Q1_A1.5@76.937,6.465
  Mid Layer 1 w0.178: v2(53.311,12.799) 53.311,10.479 57.494,6.296 v2(66.135,6.296) 66.58,5.851 74.246,5.851 74.605,6.211 74.605,6.303 74.964,6.662 v2@76.262,6.662
GPIO3_A2: J7_A2.4 J8_A2.17 Q1_A2.5 R155_A2.1 U1_A2.84 | length 78.4
  Top Layer w0.178: J8_A2.17@141.703,11.151 143.204,9.65 144.784,9.65 148.093,6.341 171.129,6.341 v2(171.135,6.346) 171.819,6.346 172.08,6.608 172.08,8.512 174.896,11.328 174.896,14.858 175.714,15.676 176.917,15.676 177.295,16.054 177.56,16.054 178.092,16.054 179.046,17.008 179.046,17.142 179.046,17.812 U1_A2.84@179.057,17.824 ; R155_A2.1@156.265,12.573 156.365,12.573 156.576,12.784 157.017,12.784 157.113,12.881 158.342,12.881 v2(158.311,12.849) ; v2(181.247,6.782) 181.326,6.782 181.533,6.576 181.876,6.576 Q1_A2.5@181.937,6.515
  Mid Layer 1 w0.178: v2(158.311,12.849) 158.311,10.529 162.494,6.346 v2(171.135,6.346) 171.58,5.901 179.246,5.901 179.605,6.261 179.605,6.353 179.964,6.712 v2@181.262,6.712
GPIO4_A1: J7_A1.3 J8_A1.18 R165_A1.2 U1_A1.83 | length 64.6
  Top Layer w0.178: J7_A1.3@57.93,12.831 56.905,12.831 56.246,12.172 56.246,10.876 v2(57.095,10.027) 57.174,10.027 57.3,9.902 R165_A1.2@58.146,9.902 ; U1_A1.83@73.657,17.774 v2(73.657,18.784)
  Mid Layer 1 w0.178: v2(57.095,10.027) 57.067,9.999 57.067,9.394 57.471,8.991 66.76,8.991 68.127,7.624 v2(68.127,7.612)
  Bottom Layer w0.178: J8_A1.18@39.243,11.101 41.207,9.136 41.207,8.71 44.001,5.917 55.104,5.917 55.248,5.773 66.352,5.773 66.904,6.325 66.904,6.381 68.127,7.605 v2(68.127,7.612) 69.853,9.337 69.853,11.452 70.449,12.048 71.094,12.693 71.094,12.822 71.714,13.443 71.714,14.376 72.221,14.882 72.221,17.348 v2(73.657,18.784)
GPIO4_A2: J7_A2.3 J8_A2.18 R165_A2.2 U1_A2.83 | length 64.6
  Top Layer w0.178: J7_A2.3@162.93,12.881 161.905,12.881 161.246,12.222 161.246,10.926 v2(162.095,10.077) 162.174,10.077 162.3,9.952 R165_A2.2@163.146,9.952 ; U1_A2.83@178.657,17.824 v2(178.657,18.834)
  Mid Layer 1 w0.178: v2(162.095,10.077) 162.067,10.049 162.067,9.444 162.471,9.041 171.76,9.041 173.127,7.674 v2(173.127,7.662)
  Bottom Layer w0.178: J8_A2.18@144.243,11.151 146.207,9.186 146.207,8.76 149.001,5.967 160.104,5.967 160.248,5.823 171.352,5.823 171.904,6.375 171.904,6.431 173.127,7.655 v2(173.127,7.662) 174.853,9.387 174.853,11.502 175.449,12.098 176.094,12.743 176.094,12.872 176.714,13.493 176.714,14.426 177.221,14.932 177.221,17.398 v2(178.657,18.834)
GPIO5_A1: J7_A1.7 J8_A1.15 R167_A1.1 U1_A1.82 | length 65
  Top Layer w0.178: J8_A1.15@36.703,13.641 38.204,12.14 39.673,12.14 40.83,10.983 40.83,9.088 43.249,6.669 63.389,6.669 64.1,7.38 65.314,7.38 66.322,8.388 v2(66.322,8.402) ; v2@66.329,8.395 69.518,11.584 69.518,14.965 70.557,16.004 71.76,16.004 72.138,16.382 72.404,16.382 72.67,16.382 73.246,16.958 73.246,17.762 U1_A1.82@73.257,17.774
  Mid Layer 1 w0.178: v2(57.17,15.384) 57.153,15.368 56.833,15.368 55.67,14.205 55.67,10.257 57.314,8.613 64.845,8.613 65.056,8.402 v2(66.322,8.402)
GPIO5_A2: J7_A2.7 J8_A2.15 R167_A2.1 U1_A2.82 | length 65
  Top Layer w0.178: J8_A2.15@141.703,13.691 143.204,12.19 144.673,12.19 145.83,11.033 145.83,9.138 148.249,6.719 168.389,6.719 169.1,7.43 170.314,7.43 171.322,8.438 v2(171.322,8.452) ; v2@171.329,8.445 174.518,11.634 174.518,15.015 175.557,16.054 176.76,16.054 177.138,16.432 177.404,16.432 177.67,16.432 178.246,17.008 178.246,17.812 U1_A2.82@178.257,17.824
  Mid Layer 1 w0.178: v2(162.26,15.421) 162.204,15.365 161.78,15.365 160.67,14.255 160.67,10.307 162.314,8.663 169.845,8.663 170.056,8.452 v2(171.322,8.452)
GPIO6_A1: C32_A1.1 J7_A1.8 J8_A1.16 R37_A1.2 R162_A1.1 | length 65.5
  Top Layer w0.178: R162_A1.1@51.25,13.845 51.25,15.275 53.764,15.275 v2(53.86,15.371)
  Mid Layer 1 w0.178: v2(53.86,15.371) 53.86,10.464 57.468,6.856 65.437,6.856 v2(65.457,6.876)
  Bottom Layer w0.178: J8_A1.16@39.243,13.641 41.434,13.641 41.585,13.489 41.585,8.867 43.826,6.627 54.477,6.627 54.727,6.876 v2(65.457,6.876) ; v2@65.447,6.914 65.54,6.82 66.55,6.82 69.475,9.746 69.475,11.608 70.479,12.613 70.666,12.8 70.666,14.388 70.773,14.495 70.773,14.818 R37_A1.2@71.159,15.204
GPIO6_A2: C32_A2.1 J7_A2.8 J8_A2.16 R37_A2.2 R162_A2.1 | length 65.5
  Top Layer w0.178: R162_A2.1@156.25,13.895 156.25,15.325 158.764,15.325 v2(158.86,15.421)
  Mid Layer 1 w0.178: v2(158.86,15.421) 158.86,10.514 162.468,6.906 170.437,6.906 v2(170.457,6.926)
  Bottom Layer w0.178: J8_A2.16@144.243,13.691 146.434,13.691 146.585,13.539 146.585,8.917 148.826,6.677 159.477,6.677 159.727,6.926 v2(170.457,6.926) ; v2@170.447,6.964 170.54,6.87 171.55,6.87 174.475,9.796 174.475,11.658 175.479,12.663 175.666,12.85 175.666,14.438 175.773,14.545 175.773,14.868 R37_A2.2@176.159,15.254
GPIO6_L_A1: R37_A1.1 U1_A1.81 | length 3.9
  Top Layer w0.178: v2(72.854,18.801) 72.855,18.799 72.855,17.775 U1_A1.81@72.857,17.774
  Bottom Layer w0.178: R37_A1.1@71.159,16.804 71.545,17.19 71.843,17.19 71.843,17.79 v2(72.854,18.801)
GPIO6_L_A2: R37_A2.1 U1_A2.81 | length 3.9
  Top Layer w0.178: v2(177.854,18.851) 177.855,18.849 177.855,17.825 U1_A2.81@177.857,17.824
  Bottom Layer w0.178: R37_A2.1@176.159,16.854 176.545,17.24 176.843,17.24 176.843,17.84 v2(177.854,18.851)
GPIO7_A1: J7_A1.9 J8_A1.13 R166_A1.1 U1_A1.80 | length 67.5
  Top Layer w0.178: J8_A1.13@36.703,16.181 38.204,14.68 39.673,14.68 41.207,13.145 41.207,9.245 43.406,7.046 63.232,7.046 64.275,8.089 v2(64.628,8.089) ; v2(64.628,8.089) 64.695,8.089 65.016,8.41 65.589,8.41 69.14,11.961 69.14,15.121 70.401,16.382 71.604,16.382 71.982,16.76 72.247,16.76 72.446,16.958 72.446,17.762 U1_A1.80@72.457,17.774
  Mid Layer 1 w0.178: v2(58.375,16.627) 56.988,16.627 55.292,14.931 55.292,10.101 57.304,8.089 v2(64.628,8.089)
  Bottom Layer w0.254: R166_A1.1@58.21,16.627 v2(58.375,16.627)
GPIO7_A2: J7_A2.9 J8_A2.13 R166_A2.1 U1_A2.80 | length 67.5
  Top Layer w0.178: J8_A2.13@141.703,16.231 143.204,14.73 144.673,14.73 146.207,13.195 146.207,9.295 148.406,7.096 168.232,7.096 169.275,8.139 v2(169.628,8.139) 169.695,8.139 170.016,8.46 170.589,8.46 174.14,12.011 174.14,15.171 175.401,16.432 176.604,16.432 176.982,16.81 177.247,16.81 177.446,17.008 177.446,17.812 U1_A2.80@177.457,17.824
  Mid Layer 1 w0.178: v2(163.375,16.677) 161.988,16.677 160.292,14.981 160.292,10.151 162.304,8.139 v2(169.628,8.139)
  Bottom Layer w0.254: R166_A2.1@163.21,16.677 v2(163.375,16.677)
GPIO8_A1: J7_A1.10 J8_A1.14 U1_A1.79 U3_A1.3 | length 87.7
  Top Layer w0.178: v2(46.794,17.134) 46.839,17.089 49.308,17.089 50.167,17.949 50.177,17.949 50.896,18.668 50.896,21.324 50.182,22.038 49.257,22.038 U3_A1.3@49.243,22.024 ; v2(72.036,18.953) 72.046,18.943 72.046,17.784 U1_A1.79@72.057,17.774
  Top Layer w0.254: J7_A1.10@53.86,16.641 53.867,16.634 55.992,16.634 v2(55.999,16.627)
  Mid Layer 1 w0.178: J8_A1.14@39.243,16.181 40.196,17.134 v2(46.794,17.134) ; v2(55.999,16.627) 54.914,15.542 54.914,9.944 57.459,7.4 65.674,7.4 65.692,7.382 66.096,7.382 v2(66.135,7.344)
  Bottom Layer w0.178: J8_A1.14@39.243,16.181 39.428,16.181 41.963,13.646 41.963,9.023 43.586,7.4 65.674,7.4 65.692,7.382 66.096,7.382 v2(66.135,7.344) ; v2@66.135,7.327 66.19,7.382 66.577,7.382 69.097,9.902 69.097,11.768 70.288,12.959 70.288,17.317 71.305,18.334 71.431,18.334 72.036,18.939 v2(72.036,18.953)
